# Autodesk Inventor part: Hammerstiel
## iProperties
Created: 2005-12
Part Number: Hammerstiel
Document SubType Name: Modeling
Designer: Benno
Manufacturer: Standard
Standards Organization: Custom
Author: Benno
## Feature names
1. Extrusion1
2. Extrusion2
3. Extrusion3
4. Flächenverjüngung1
5. Extrusion4
6. Extrusion5
7. Bohrung1 [Hole]
8. Bohrung2 [Hole]
9. Rundung3 [Fillet]
10. Rundung4 [Fillet]
